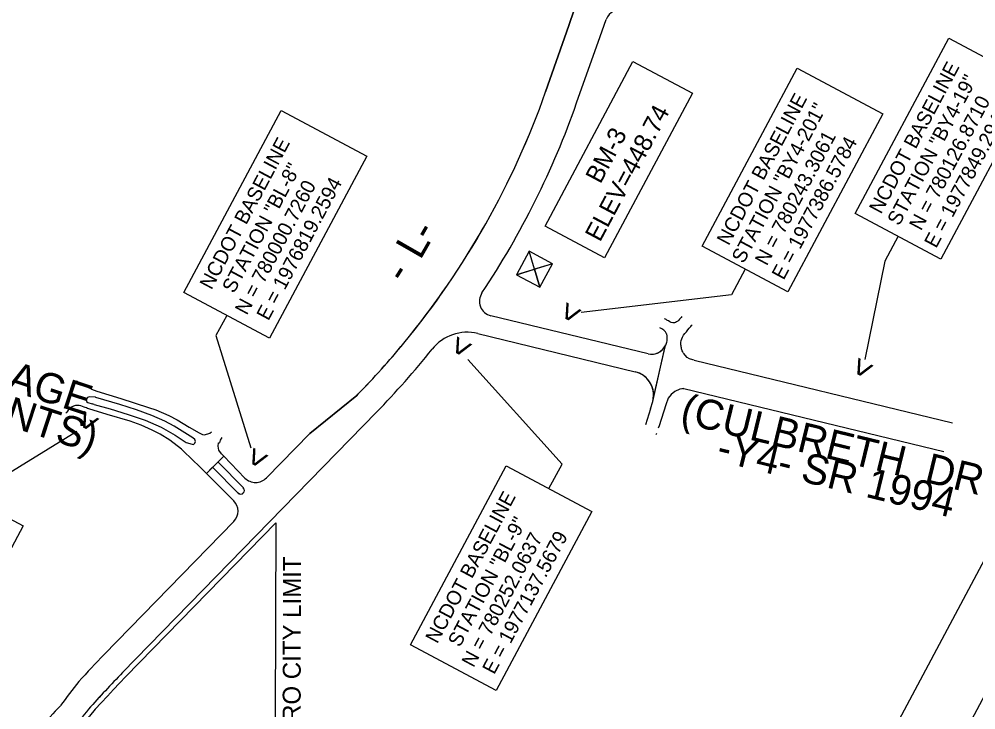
# Model space of a CAD drawing. Extents: x 1970823 to 1988115, y 770601 to 786368.
# Drawn here: x 1976409 to 1978006, y 779627 to 780780 of the extents above; entities that cross this region are included whole.
import ezdxf

# ---------------------------------------------------------------- set-up
doc = ezdxf.new("R2010")
doc.units = 0
for name, color, linetype in [('CTL Sheet Border CELL', 7, 'Continuous'), ('CTL Sheet Text', 7, 'Continuous'), ('CTL Supplemental Horizontal and Vertical Text', 7, 'Continuous'), ('Default', 7, 'Continuous'), ('Old_Level_1', 7, 'Continuous'), ('Old_Level_12', 7, 'Continuous'), ('Old_Level_3', 7, 'Continuous'), ('Old_Level_32', 7, 'Continuous'), ('Old_Level_57', 7, 'Continuous')]:
    doc.layers.add(name, color=color, linetype=linetype)

msp = doc.modelspace()

# ---------------------------------------------------------------- linework, layer by layer
at = {"layer": 'CTL Sheet Border CELL'}
msp.add_lwpolyline([(1977121.9, 778191.4), (1979828.5, 783270.4), (1979922.1, 783220.5), (1977215.6, 778141.6)], close=True, dxfattribs=at)
at = {"layer": 'CTL Supplemental Horizontal and Vertical Text'}
for points in [[(1977875.9, 780417.5), (1977853.8, 780376.1), (1977820.3, 780211.9)], [(1977620.5, 780362.6), (1977597.7, 780319.8), (1977346.8, 780290.3)], [(1976755.5, 780285.3), (1976737.4, 780251.5), (1976795.7, 780064.4)], [(1977293, 779996.1), (1977315, 780037.2), (1977157.6, 780211.5)], [(1976344.2, 779972), (1976360.9, 780003.3), (1976505.3, 780092.2)]]:
    msp.add_lwpolyline(points, dxfattribs=at)
at = {"layer": 'Default'}
for p, q in [((1977326.5, 780769.3), (1977335.4, 780795.5)), ((1977287.5, 780658.4), (1977326.5, 780769.3)), ((1977378.4, 780751), (1977388.8, 780779.5)), ((1977339.4, 780640.2), (1977378.4, 780751)), ((1977458.6, 780221.1), (1977196.3, 780284.7)), ((1977174.4, 780255.1), (1977437.2, 780191.3)), ((1977466.3, 780141.6), (1977487.7, 780236.1)), ((1976894, 780088.4), (1976972.4, 780151.6)), ((1976972.4, 780151.6), (1976974.3, 780153.6)), ((1977462.9, 780129.4), (1977466.3, 780141.6)), ((1976581.6, 779689), (1977005.1, 780123.6)), ((1976821.5, 780013.9), (1976894, 780088.4)), ((1976721.5, 780021.5), (1976750.3, 780050.1)), ((1976750.3, 780050.1), (1976785.8, 780013.8)), ((1976732.2, 780031.6), (1976774.5, 779988.8)), ((1976740.9, 780040.3), (1976783.1, 779997.3)), ((1976721.5, 780021.5), (1976767, 779976)), ((1976550.8, 779719), (1976767.1, 779941))]:
    msp.add_line(p, q, dxfattribs=at)
for points in [[(1977335.4, 780795.5), (1977326.5, 780769.3), (1977287.5, 780658.4)], [(1977339.4, 780640.2), (1977378.4, 780751), (1977388.8, 780779.5)], [(1977458.6, 780221.1), (1977196.3, 780284.7)], [(1977174.4, 780255.1), (1977437.2, 780191.3)], [(1977050.9, 780239), (1977050.8, 780238.9)], [(1977467.2, 780145.7), (1977487, 780233), (1977486.5, 780233.1), (1977486.3, 780233.2)], [(1976974.3, 780153.6), (1976972.4, 780151.6), (1976894, 780088.4), (1976821.5, 780013.9)], [(1976581.6, 779689), (1977005.1, 780123.6)], [(1976785.8, 780013.8), (1976750.3, 780050.1), (1976740.7, 780040.5), (1976740.9, 780040.3), (1976783.1, 779997.3)], [(1976774.5, 779988.8), (1976732.2, 780031.6), (1976731.9, 780031.9), (1976721.5, 780021.5), (1976767, 779976)], [(1976782.9, 779988.8), (1976783, 779988.8)], [(1976767.1, 779941), (1976550.8, 779719)], [(1976524.7, 779628), (1976524.8, 779628.1)]]:
    msp.add_lwpolyline(points, dxfattribs=at)
for points in [[(1977804.4, 780455.6), (1977960.4, 780748.3), (1978103.4, 780672.1), (1977947.4, 780379.4)], [(1977286.9, 780434.1), (1977433.4, 780709.1), (1977532.6, 780656.1), (1977386.1, 780381.2)], [(1977549.1, 780400.7), (1977707.5, 780698), (1977850.5, 780621.8), (1977692, 780324.5)], [(1976684, 780323.4), (1976846, 780627.4), (1976989, 780551.2), (1976827, 780247.3)], [(1977062.2, 779735.2), (1977221.5, 780034.2), (1977364.5, 779958), (1977205.2, 779659)], [(1976111.7, 779707.7), (1976272.8, 780010.1), (1976415.7, 779933.9), (1976254.6, 779631.6)]]:
    msp.add_lwpolyline(points, close=True, dxfattribs=at)
for centre, radius, start, end in [((1977412.3, 780770.9), 25, 71.6828, 159.9103), ((1977412.3, 780770.9), 25, 71.6828, 159.9103), ((1975987.1, 781115.7), 1378.5, 320.501, 340.6265), ((1975987.1, 781115.7), 1378.5, 320.5086, 340.6265), ((1975987.1, 781115.7), 1433.5, 326.4217, 340.6265), ((1975987.1, 781115.7), 1433.5, 326.4217, 340.6265), ((1977202.2, 780309), 25, 146.4217, 256.3665), ((1977202.2, 780309), 25, 146.4217, 256.3665), ((1977156.7, 780182.2), 75, 76.3665, 141.4059), ((1977156.7, 780182.2), 75, 76.3665, 141.4059), ((1975987.1, 781115.7), 1378.5, 315.7395, 320.5086), ((1975987.1, 781115.7), 1378.5, 315.7395, 320.501), ((1975987.1, 781115.7), 1421.5, 315.7395, 321.4059), ((1975987.1, 781115.7), 1421.5, 315.7395, 321.4059), ((1977464.5, 780245.4), 25, 256.3665, 338.0093), ((1977464.5, 780245.4), 25, 256.3665, 330.6957), ((1977427.8, 780152.4), 40, 344.2788, 76.3665), ((1977427.8, 780152.4), 40, 350.2502, 76.3665), ((1976803.6, 780031.4), 25, 224.7243, 315.7395), ((1976803.6, 780031.4), 25, 224.7243, 315.7395), ((1976778.8, 779993.1), 6, 314.6608, 44.4765), ((1976778.8, 779993.1), 6, 314.6608, 44.4765), ((1976778.8, 779993.1), 6, 224.6608, 314.6607), ((1976778.7, 779993), 6, 224.6608, 314.6608), ((1976778.8, 779993.1), 6, 314.6607, 314.6608), ((1976749.2, 779958.4), 25, 315.7395, 44.7243), ((1976749.2, 779958.4), 25, 315.7395, 44.7243), ((1977926.9, 778377.9), 1921.5, 135.7395, 137.5783), ((1977926.9, 778377.9), 1921.5, 135.7395, 137.5783), ((1977926.9, 778377.9), 1878.5, 135.7395, 138.2839), ((1977926.9, 778377.9), 1878.5, 135.7395, 138.2814), ((1978028, 778491.5), 1925.5, 142.1057, 143.6134), ((1978028, 778491.5), 1925.5, 142.1057, 143.6134), ((1977876.3, 778316.7), 1921, 136.7176, 139.7332), ((1977876.3, 778316.7), 1921, 136.7176, 139.7332), ((1977976, 778436), 1878, 140.5977, 142.0125), ((1977976, 778436), 1878, 140.6002, 142.0125), ((1977926.9, 778377.9), 1878.5, 138.2814, 138.2839), ((1977976, 778436), 1878, 140.5977, 140.6002)]:
    msp.add_arc(centre, radius, start, end, dxfattribs=at)
at = {"layer": 'Old_Level_12'}
msp.add_line((1976586.9, 779682.3), (1976837.1, 779939), dxfattribs=at)
msp.add_lwpolyline([(1976837.1, 779939), (1976836.2, 779613), (1976837.5, 779325.2)], dxfattribs=at)
msp.add_arc((1977861.3, 778440.4), 1779.3, 135.7394, 143.4363, dxfattribs=at)
at = {"layer": 'Old_Level_3'}
for p, q in [((1977535.3, 780210.4), (1977966.9, 780105.7)), ((1977518.2, 780163.1), (1977952, 780057.9)), ((1976741.8, 780072.8), (1976743.5, 780072.4)), ((1976714.7, 780028.1), (1976707.6, 780035.1))]:
    msp.add_line(p, q, dxfattribs=at)
for points in [[(1977487.5, 780279.1), (1977485.8, 780279.8)], [(1977535.3, 780210.4), (1977533.1, 780210.9), (1977527.9, 780212.6), (1977523.6, 780215.3), (1977517.8, 780222)], [(1976529.4, 780161.9), (1976522.5, 780165.3), (1976512.6, 780170.3), (1976504.5, 780175.3)], [(1976529.4, 780161.9), (1976538.6, 780158.7)], [(1976538.7, 780158.7), (1976578.5, 780146.5), (1976625, 780131.8), (1976637.2, 780127.8), (1976659, 780118.3), (1976672.7, 780110.9), (1976692.5, 780098.5), (1976709.1, 780089.3), (1976715.2, 780086.5), (1976718.4, 780086.2), (1976727.1, 780088.7), (1976729.7, 780091.2)], [(1977516.1, 780163.2), (1977518.2, 780163.1), (1977511.5, 780161.9), (1977503.1, 780158.1), (1977497.1, 780153.2), (1977492.4, 780147.1), (1977488, 780135.9), (1977477, 780100.7), (1977475.6, 780096.8)], [(1976536.8, 780148.5), (1976536.3, 780148.6), (1976526, 780149.2), (1976522.8, 780148.1), (1976520.6, 780145.3), (1976521.4, 780141.5), (1976523.7, 780139.7), (1976530.7, 780137.6)], [(1976534, 780136.8), (1976560.6, 780129.2), (1976590.8, 780119.7), (1976619.3, 780110.4), (1976645.7, 780098.8), (1976669.4, 780085.3), (1976687.6, 780073.4), (1976697.7, 780070.1), (1976700.1, 780069.9), (1976702, 780072), (1976703.2, 780074.7), (1976702, 780078), (1976698.9, 780080.9), (1976667.7, 780100.5), (1976651.9, 780109), (1976630.4, 780118.4), (1976604.9, 780127.7), (1976577.2, 780136.7), (1976536.9, 780148.4)], [(1976707.6, 780035.1), (1976700.6, 780042.1), (1976679.8, 780062.2), (1976660.3, 780077.1), (1976644.1, 780086.9), (1976630.8, 780093.7), (1976612.5, 780102), (1976594.1, 780108.5), (1976555.9, 780120), (1976525.3, 780129.2)], [(1976534, 780136.8), (1976530.8, 780137.6)], [(1977462.9, 780129.4), (1977454.1, 780102.5)], [(1976747.3, 780081.4), (1976744.7, 780076.8), (1976743.5, 780072.4)], [(1977472.6, 780088.2), (1977471.8, 780086.1)], [(1976750.3, 780050.1), (1976746.4, 780054.1), (1976742.3, 780060.1), (1976741, 780067.2), (1976741.8, 780072.8)], [(1976721.5, 780021.5), (1976714.7, 780028.1)]]:
    msp.add_lwpolyline(points, dxfattribs=at)
msp.add_ellipse((1977473.4, 780247.6), major_axis=(7.3, 15.9), ratio=0.997463, start_param=5.549024, end_param=6.436834, dxfattribs=at)
for points in [[(1977514.9, 780283.5), (1977509.7, 780277.4), (1977502.5, 780273.1), (1977492.5, 780276), (1977487.5, 780279.1)], [(1977517.9, 780252.3), (1977527.3, 780263.9), (1977532.2, 780269.8)], [(1977489.6, 780254.3), (1977489.2, 780239.9), (1977488.4, 780237), (1977486.5, 780233.1)], [(1977517.3, 780222.6), (1977514.5, 780229.5), (1977513.9, 780232.6), (1977513.3, 780240.2), (1977517.7, 780252.1)], [(1976525.1, 780129.4), (1976517.2, 780132.2), (1976506.1, 780135.1), (1976499.7, 780133.7), (1976491.9, 780128.3), (1976487.1, 780122.3)]]:
    msp.add_spline(points, degree=3, dxfattribs=at)
at = {"layer": 'Old_Level_57'}
for p, q in [((1977278.2, 780332.5), (1977260, 780392.3)), ((1977299, 780371.5), (1977239.2, 780353.3))]:
    msp.add_line(p, q, dxfattribs=at)
msp.add_lwpolyline([(1977260, 780392.3), (1977239.2, 780353.3), (1977278.2, 780332.5), (1977299, 780371.5)], close=True, dxfattribs=at)
for points in [[(1977269.1, 780362.4), (1977260, 780392.3), (1977239.2, 780353.3), (1977269.1, 780362.4)], [(1977269.1, 780362.4), (1977278.2, 780332.5), (1977299, 780371.5), (1977269.1, 780362.4)]]:
    msp.add_lwpolyline(points, dxfattribs=at)

# ---------------------------------------------------------------- texts
at = {"layer": 'CTL Sheet Text'}
for s, rotation, p in [('(THE VILLAGE', 341.8664, (1976089.7, 780259.4)), ('APARTMENTS)', 341.8664, (1976075, 780203.8)), ('(CULBRETH  DR.)', 346.3665, (1977510.2, 780106.5)), ('-Y4- SR 1994', 346.3665, (1977570.6, 780043.1))]:
    msp.add_text(s, height=50, rotation=rotation, dxfattribs=at).set_placement(p)
at = {"layer": 'CTL Supplemental Horizontal and Vertical Text'}
for s, height, p in [('NCDOT BASELINE', 24, (1977847.4, 780453.3)), ('STATION "BY4-19"', 24, (1977877.7, 780433.6)), ('NCDOT BASELINE', 24, (1977593.2, 780400.7)), ('STATION "BY4-201"', 24, (1977618, 780370.6)), ('N = 780126.8710', 24, (1977914.2, 780425.5)), ('E = 1977849.2947', 24, (1977939.4, 780396.2)), ('ELEV=448.74', 30, (1977378.4, 780406.6)), ('BM-3', 30, (1977379.1, 780503.6)), ('N = 780243.3061', 24, (1977656.8, 780366.9)), ('NCDOT BASELINE', 24, (1976730, 780326.8)), ('E = 1977386.5784', 24, (1977684.9, 780343.1)), ('STATION "BL-8"', 24, (1976767.5, 780320.8)), ('N = 780000.7260', 24, (1976789, 780284.5)), ('E = 1976819.2594', 24, (1976824.9, 780275.2)), ('NCDOT BASELINE', 24, (1977106.8, 779736)), ('STATION "BL-9"', 24, (1977144.4, 779730)), ('N = 780252.0637', 24, (1977167.2, 779696.2)), ('E = 1977137.5679', 24, (1977201.7, 779684.5))]:
    msp.add_text(s, height=height, rotation=61.9471, dxfattribs=at).set_placement(p)
at = {"layer": 'Old_Level_1'}
for s, rotation, p in [('-', 60.1322, (1977096, 780407.2)), ('L', 60.1322, (1977078.4, 780376.5)), ('-', 57.598, (1977053.3, 780336.5))]:
    msp.add_text(s, height=50, rotation=rotation, dxfattribs=at).set_placement(p)
at = {"layer": 'Old_Level_32'}
msp.add_text('CARRBORO CITY LIMIT', height=30, rotation=89.85, dxfattribs=at).set_placement((1976878.2, 779434.9))
at = {"layer": 'Old_Level_57'}
for p in [(1977319.8, 780311.7), (1977137.2, 780254.6), (1977807, 780219.2), (1976514.8, 780130.3), (1976797.1, 780069)]:
    msp.add_text('>', height=39.1, rotation=241.9613, dxfattribs=at).set_placement(p)

doc.saveas('drawing.dxf')
